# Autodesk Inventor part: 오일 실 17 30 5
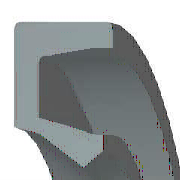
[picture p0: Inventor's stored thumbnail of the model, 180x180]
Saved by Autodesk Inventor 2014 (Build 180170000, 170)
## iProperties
IsCustomPart: 1
Created: 2012-02
Part Number: 오일 실 17 30 5
Material: 고무
Description: 오일 실 - 비스프링, 금속 케이스 GM
Document SubType Name: Modeling
Standard: JIS B 2402
Designer: mduedu
Standards Organization: JIS
Language: ko-KR
Size Designation: 17 30 5 B
Categories: <MemberInstance><Categories><Category DisplayName="샤프트 부품" InternalName="7f7aeb1f-a693-4053-b835-cee3144e0d98" Mnemonic="SHFT"><Category DisplayName="실링" Intern
Density: 0.93 g/cm^3
Appearance: Rubber-Black
Mass: 0.924459 g
Surface Area: 18.6212 cm^2
Volume: 0.994042 cm^3
Author: mduedu
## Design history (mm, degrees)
body "Solid1"
revolve "회전1" stored, may be unused: angle "d27" = 360 deg
fillet "모깎기1" dims "d28" = 0.25 (= 0.05 x b)
chamfer "모따기1" distance "d29" = 0.07143 (= 0.0142857 x b); stored, may be unused: second distance "d30" = 0.25 (= 0.05 x b), angle "d35" = 45 deg
sketch "스케치2"
  geometry: L1 (-9.367, -3.238)-(-10.233, -3.863); L2 (-8.5, -1.625)-(-9.367, -3.238); L3 (-9.15, -1)-(-8.5, -1.625); L4 (-11.317, -3.75)-(-9.15, -1); L5 (-13.075, -3.75)-(-11.317, -3.75); L6 (-14.375, -1.25)-(-13.075, -3.75); L7 (-14.375, 0)-(-14.375, -1.25); L8 (-15, 0)-(-14.375, 0); L9 (-15, -5)-(-15, 0); L10 (-11.129, -5)-(-15, -5); L11 (-10.233, -3.863)-(-11.129, -5); L12 (0, -9.6)-(0, 1.6) reference; L13 (-14, 0)-(-28, 0) reference
  constraints: 22 end point, 3 horizontal, 2 vertical, 1 parallel
  dimensions: "d2" = 5 distance of L9.start L8.start (= b); "d4" = 1 vertical distance of L8.start L3.start (= 0.2 x b); "d6" = 0.625 distance of L8.start L7.start (= 0.125 x b); "d8" = 1.25 distance of L7.start L6.start (= 0.25 x b); "d10" = 1.25 vertical distance of L5.start L9.start (= 0.25 x b); "d12" = 1.3 horizontal distance of L6.start L5.start (= 0.1 x dd - 0.1 x Diam); "d14" = 1.6129 vertical distance of L2.start L1.start (= 0.322581 x b); "d16" = 0.86667 horizontal distance of L1.start L1.end (= 0.0666667 x dd - 0.0666667 x Diam); "d18" = 0.86667 horizontal distance of L2.start L1.start (= 0.0666667 x dd - 0.0666667 x Diam); "d20" = 0.625 vertical distance of L3.start L2.start (= 0.125 x b); "d22" = 0.65 horizontal distance of L3.start L2.start (= 0.05 x dd - 0.05 x Diam); "d24" = 0.625 vertical distance of L1.start L1.end (= 0.125 x b); "d26" = 2.16667 horizontal distance of L4.start L3.start (= 0.166667 x dd - 0.166667 x Diam); "d31" = 0 distance between parallel lines of L8 L13; "d32" = 15 distance between parallel lines of L12 L9 (= 0.5 x dd); "d33" = 8.5 distance from line of L12 L2.start (= 0.5 x Diam)
other parameters: "Diam" = 17 [user parameter; used in 6 equation terms], "b" = 5 [user parameter; used in 11 equation terms], "d1" = 8 (derived), "d3" = 1.6 (derived), "d5" = 1 (derived), "d7" = 2 (derived), "d9" = 2 (derived), "d11" = 2 (derived), "d13" = 2.58065 (derived), "d15" = 1.33333 (derived), "d17" = 1.33333 (derived), "d19" = 1 (derived), "d21" = 1 (derived), "d23" = 1 (derived), "d25" = 3.33333 (derived), "d34" = 0
